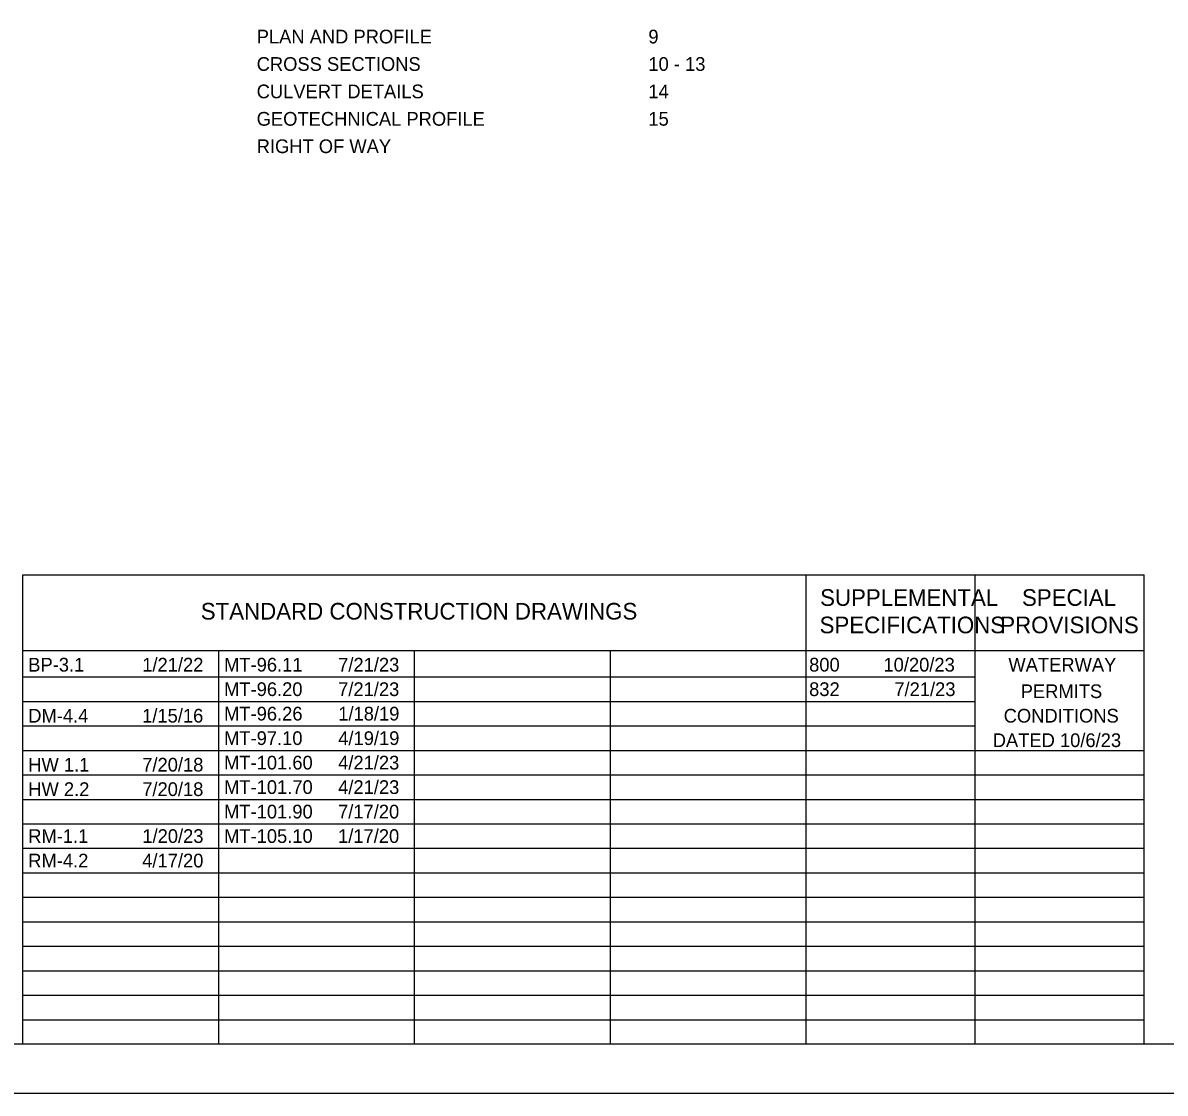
# Model space of a CAD drawing. Extents: x 0 to 34, y 0 to 22.
# Drawn here: x 12.37 to 24.04, y 0 to 10.93 of the extents above; entities that cross this region are included whole.
import ezdxf

# ---------------------------------------------------------------- set-up
doc = ezdxf.new("R2010")
doc.units = 0
for name, color, linetype in [('SH_Border', 7, 'Continuous'), ('SH_Cut_Line', 7, 'Continuous'), ('SH_Data', 7, 'Continuous'), ('SH_Text', 7, 'Continuous')]:
    doc.layers.add(name, color=color, linetype=linetype)

msp = doc.modelspace()

# ---------------------------------------------------------------- linework, layer by layer
at = {"layer": 'SH_Border'}
msp.add_lwpolyline([(1.5, 21.5), (33.5, 21.5), (33.5, 0.5), (1.5, 0.5)], close=True, dxfattribs=at)
at = {"layer": 'SH_Cut_Line'}
msp.add_lwpolyline([(0, 0), (34, 0), (34, 22), (0, 22)], close=True, dxfattribs=at)
at = {"layer": 'SH_Data'}
for p, q in [((12.375, 5.292), (23.825, 5.292)), ((12.375, 0.5), (12.375, 5.292)), ((20.375, 0.5), (20.375, 5.292)), ((22.1, 0.5), (22.1, 5.292)), ((23.825, 0.5), (23.825, 5.292)), ((12.375, 0.5), (12.375, 4.521)), ((12.375, 4.521), (23.825, 4.521)), ((14.375, 0.5), (14.375, 4.521)), ((16.375, 0.5), (16.375, 4.521)), ((18.375, 0.5), (18.375, 4.521)), ((12.375, 4.25), (22.1, 4.25)), ((12.375, 4), (22.1, 4)), ((12.375, 3.75), (22.1, 3.75)), ((12.375, 3.5), (23.825, 3.5)), ((12.375, 3.25), (23.825, 3.25)), ((12.375, 3), (23.825, 3)), ((12.375, 2.75), (23.825, 2.75)), ((12.375, 2.5), (23.825, 2.5)), ((12.375, 2.25), (23.825, 2.25)), ((12.375, 2), (23.825, 2)), ((12.375, 1.75), (23.825, 1.75)), ((12.375, 1.5), (23.825, 1.5)), ((12.375, 1.25), (23.825, 1.25)), ((12.375, 1), (23.825, 1)), ((12.375, 0.75), (23.825, 0.75))]:
    msp.add_line(p, q, dxfattribs=at)

# ---------------------------------------------------------------- texts
at = {"layer": 'SH_Text'}
for s, height, p in [('PLAN AND PROFILE', 0.14, (14.763, 10.719)), ('9', 0.14, (18.763, 10.719)), ('CROSS SECTIONS', 0.14, (14.763, 10.439)), ('10 - 13', 0.14, (18.763, 10.439)), ('CULVERT DETAILS', 0.14, (14.763, 10.159)), ('14', 0.14, (18.763, 10.159)), ('GEOTECHNICAL PROFILE', 0.14, (14.763, 9.879)), ('15', 0.14, (18.763, 9.879)), ('RIGHT OF WAY', 0.14, (14.763, 9.599)), ('SUPPLEMENTAL', 0.17, (20.517, 4.976)), ('SPECIAL', 0.17, (22.579, 4.976)), ('STANDARD CONSTRUCTION DRAWINGS', 0.17, (14.192, 4.836)), ('SPECIFICATIONS', 0.17, (20.512, 4.696)), ('PROVISIONS', 0.17, (22.357, 4.696)), ('BP-3.1', 0.14, (12.43, 4.305)), ('1/21/22', 0.14, (13.594, 4.305)), ('MT-96.11', 0.14, (14.43, 4.305)), ('7/21/23', 0.14, (15.595, 4.305)), ('800', 0.14, (20.405, 4.305)), ('10/20/23', 0.14, (21.164, 4.305)), ('WATERWAY', 0.14, (22.44, 4.305)), ('7/21/23', 0.14, (15.595, 4.055)), ('7/21/23', 0.14, (21.275, 4.055)), ('MT-96.20', 0.14, (14.43, 4.055)), ('832', 0.14, (20.405, 4.055)), ('PERMITS', 0.14, (22.566, 4.034)), ('DM-4.4', 0.14, (12.43, 3.784)), ('1/15/16', 0.14, (13.593, 3.784)), ('MT-96.26', 0.14, (14.43, 3.805)), ('1/18/19', 0.14, (15.596, 3.805)), ('CONDITIONS', 0.14, (22.392, 3.784)), ('MT-97.10', 0.14, (14.43, 3.555)), ('4/19/19', 0.14, (15.596, 3.555)), ('DATED 10/6/23', 0.14, (22.28, 3.534)), ('HW 1.1', 0.14, (12.43, 3.284)), ('7/20/18', 0.14, (13.594, 3.284)), ('MT-101.60', 0.14, (14.43, 3.305)), ('4/21/23', 0.14, (15.595, 3.305)), ('HW 2.2', 0.14, (12.43, 3.034)), ('7/20/18', 0.14, (13.594, 3.034)), ('MT-101.70', 0.14, (14.43, 3.055)), ('4/21/23', 0.14, (15.595, 3.055)), ('MT-101.90', 0.14, (14.43, 2.805)), ('7/17/20', 0.14, (15.594, 2.805)), ('RM-1.1', 0.14, (12.43, 2.555)), ('1/20/23', 0.14, (13.595, 2.555)), ('MT-105.10', 0.14, (14.43, 2.555)), ('1/17/20', 0.14, (15.594, 2.555)), ('4/17/20', 0.14, (13.594, 2.305)), ('RM-4.2', 0.14, (12.43, 2.305))]:
    msp.add_text(s, height=height, dxfattribs=at).set_placement(p)

doc.saveas('drawing.dxf')
